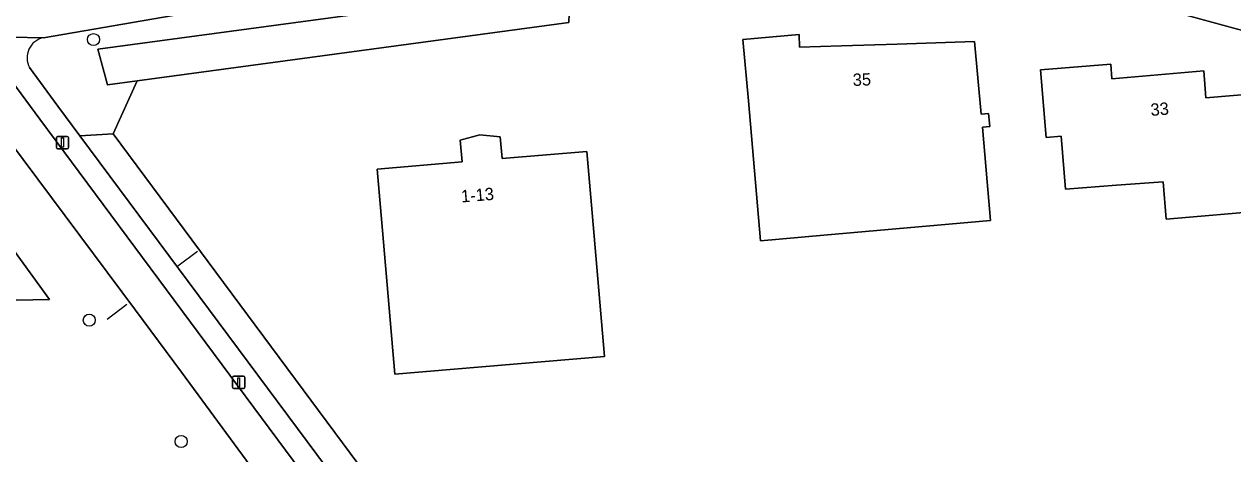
# Model space of a CAD drawing. Extents: x 163426 to 164192, y 380329 to 381641.
# Drawn here: x 163929.3 to 164027.2, y 381022.4 to 381057.2 of the extents above; entities that cross this region are included whole.
import ezdxf

# ---------------------------------------------------------------- set-up
doc = ezdxf.new("R2010")
doc.units = 0
for name, color, linetype in [('IMGEO_Boom', 7, 'Continuous'), ('IMGEO_Erf', 7, 'Continuous'), ('IMGEO_Fietspad_open', 7, 'Continuous'), ('IMGEO_Groenvoorziening', 7, 'Continuous'), ('IMGEO_Hek', 7, 'Continuous'), ('IMGEO_Lichtmast', 7, 'Continuous'), ('IMGEO_Pand', 7, 'Continuous'), ('IMGEO_Pand_nummerreeks', 7, 'Continuous'), ('IMGEO_Voetpad_open', 7, 'Continuous'), ('IMGEO_Waterloop', 7, 'Continuous')]:
    doc.layers.add(name, color=color, linetype=linetype)

msp = doc.modelspace()

# ---------------------------------------------------------------- linework, layer by layer
at = {"layer": 'IMGEO_Boom'}
for centre in [(163934.865, 381055.935), (163934.525, 381033.187), (163941.967, 381023.352)]:
    msp.add_circle(centre, 0.489, dxfattribs=at)
at = {"layer": 'IMGEO_Erf'}
for points in [[(163985.881, 381065.478), (163983.854, 381065.112), (163984.176, 381061.429), (163980.662, 381061.081), (163975.886, 381060.609), (163976.037, 381058.881), (163973.427, 381058.717), (163973.385, 381057.316), (163938.396, 381052.589), (163936.474, 381048.305), (163965.302, 381009.415), (163968.142, 381005.578), (163988.801, 381010.675), (164000, 381012.925), (164008.796, 381014.693), (164009.7, 381016.026), (164011.181, 381014.28), (164018.059, 381014.961)], [(164043.334, 381052.508), (164030.06, 381056.092), (164000, 381064.325), (163998.958, 381064.61)]]:
    msp.add_lwpolyline(points, dxfattribs=at)
for points in [[(164007.555, 381041.264), (163994.055, 381040.08), (163988.924, 381039.63), (163987.93, 381050.973), (163987.494, 381055.953), (163992.048, 381056.338), (163992.062, 381055.311), (163995.474, 381055.422), (164000, 381055.569), (164006.256, 381055.772), (164006.802, 381049.899), (164007.399, 381049.95), (164007.493, 381048.875), (164006.894, 381048.822), (164007.199, 381045.335)], [(164021.799, 381041.375), (164021.544, 381044.41), (164017.775, 381044.125), (164013.628, 381043.811), (164013.269, 381048.094), (164012.073, 381047.993), (164011.614, 381053.471), (164017.291, 381053.948), (164017.39, 381052.763), (164024.83, 381053.387), (164025.011, 381051.208), (164029.159, 381051.553), (164029.579, 381046.571), (164029.957, 381042.08)], [(163976.272, 381030.236), (163959.272, 381028.818), (163958.277, 381040.458), (163957.849, 381045.441), (163964.738, 381046.025), (163964.569, 381047.787), (163966.173, 381048.199), (163967.823, 381048.056), (163967.969, 381046.291), (163974.846, 381046.87), (163975.273, 381041.889)]]:
    msp.add_lwpolyline(points, close=True, dxfattribs=at)
at = {"layer": 'IMGEO_Fietspad_open'}
for points in [[(163966.446, 381001.057), (163930.523, 381049.491), (163926.717, 381054.622), (163925.556, 381056.187)], [(163923.219, 381054.202), (163924.27, 381052.792), (163924.402, 381052.616), (163926.35, 381050.002), (163928.061, 381047.708), (163938.279, 381034.003), (163942.009, 381028.965), (163953.161, 381013.78), (163961.45, 381002.494)]]:
    msp.add_lwpolyline(points, dxfattribs=at)
at = {"layer": 'IMGEO_Groenvoorziening'}
for points in [[(163975.886, 381060.609), (163980.662, 381061.081), (163980.593, 381061.81), (163977.128, 381061.219), (163976.661, 381063.908), (163971.248, 381063.001), (163957.475, 381060.692), (163930.805, 381056.087)], [(163929.685, 381053.658), (163931.981, 381050.546), (163933.77, 381048.138), (163936.474, 381048.305), (163938.396, 381052.589), (163936.002, 381052.266), (163935.728, 381053.26), (163935.208, 381055.15), (163971.524, 381060.07), (163973.475, 381060.334), (163973.427, 381058.717), (163976.037, 381058.881), (163975.886, 381060.609)], [(163942.009, 381028.965), (163938.279, 381034.003), (163928.061, 381047.708), (163926.35, 381050.002), (163923.656, 381045.375), (163931.3, 381034.851), (163923.206, 381034.692), (163914.286, 381019.455)], [(163961.45, 381002.494), (163953.161, 381013.78), (163942.009, 381028.965)]]:
    msp.add_lwpolyline(points, dxfattribs=at)
for points in [[(163936.474, 381048.305), (163933.77, 381048.138), (163965.814, 381005.004), (163968.142, 381005.578), (163965.302, 381009.415)], [(163904.614, 381014.127), (163918.118, 381011.99), (163914.286, 381019.455), (163923.206, 381034.692), (163931.3, 381034.851), (163923.656, 381045.375), (163922.795, 381043.895), (163906.633, 381016.132), (163905.062, 381016.099)]]:
    msp.add_lwpolyline(points, close=True, dxfattribs=at)
msp.add_arc((163931.144, 381054.458), 1.664, 101.76009, 208.73152, dxfattribs=at)
at = {"layer": 'IMGEO_Hek'}
for points in [[(163943.306, 381038.754), (163941.702, 381037.553)], [(163937.569, 381034.464), (163935.977, 381033.256)]]:
    msp.add_lwpolyline(points, dxfattribs=at)
at = {"layer": 'IMGEO_Lichtmast'}
for p, q in [((163931.857, 381047.187), (163931.857, 381047.987)), ((163931.857, 381047.987), (163931.857, 381047.187)), ((163931.957, 381048.087), (163932.747, 381048.087)), ((163932.747, 381048.087), (163931.957, 381048.087)), ((163932.847, 381047.987), (163932.847, 381047.187)), ((163932.847, 381047.187), (163932.847, 381047.987)), ((163932.747, 381047.087), (163931.957, 381047.087)), ((163931.957, 381047.087), (163932.747, 381047.087)), ((163946.141, 381027.746), (163946.141, 381028.546)), ((163946.141, 381028.546), (163946.141, 381027.746)), ((163946.241, 381028.646), (163947.031, 381028.646)), ((163947.031, 381028.646), (163946.241, 381028.646)), ((163947.131, 381028.546), (163947.131, 381027.746)), ((163947.131, 381027.746), (163947.131, 381028.546)), ((163947.031, 381027.646), (163946.241, 381027.646)), ((163946.241, 381027.646), (163947.031, 381027.646))]:
    msp.add_line(p, q, dxfattribs=at)
for points in [[(163932.277, 381047.962), (163932.427, 381047.962), (163932.427, 381047.212), (163932.277, 381047.212), (163932.277, 381047.962)], [(163946.561, 381028.521), (163946.711, 381028.521), (163946.711, 381027.771), (163946.561, 381027.771), (163946.561, 381028.521)]]:
    msp.add_lwpolyline(points, dxfattribs=at)
for centre, start, end in [((163931.957, 381047.987), 90, 180), ((163931.957, 381047.987), 90, 180), ((163932.747, 381047.987), 0, 90), ((163932.747, 381047.987), 360, 90), ((163931.957, 381047.187), 180, 270), ((163931.957, 381047.187), 180, 270), ((163932.747, 381047.187), 270, 0), ((163932.747, 381047.187), 270, 0), ((163946.241, 381028.546), 90, 180), ((163946.241, 381028.546), 90, 180), ((163947.031, 381028.546), 0, 90), ((163947.031, 381028.546), 360, 90), ((163946.241, 381027.746), 180, 270), ((163946.241, 381027.746), 180, 270), ((163947.031, 381027.746), 270, 0), ((163947.031, 381027.746), 270, 0)]:
    msp.add_arc(centre, 0.1, start, end, dxfattribs=at)
at = {"layer": 'IMGEO_Pand'}
for points in [[(164006.256, 381055.772), (164000, 381055.569), (163995.474, 381055.422), (163992.062, 381055.311), (163992.048, 381056.338), (163987.494, 381055.953), (163987.93, 381050.973), (163988.924, 381039.63), (163994.055, 381040.08), (164007.555, 381041.264), (164007.199, 381045.335), (164006.894, 381048.822), (164007.493, 381048.875), (164007.399, 381049.95), (164006.802, 381049.899)], [(164029.159, 381051.553), (164025.011, 381051.208), (164024.83, 381053.387), (164017.39, 381052.763), (164017.291, 381053.948), (164011.614, 381053.471), (164012.073, 381047.993), (164013.269, 381048.094), (164013.628, 381043.811), (164017.775, 381044.125), (164021.544, 381044.41), (164021.799, 381041.375), (164029.957, 381042.08), (164029.579, 381046.571)], [(163959.272, 381028.818), (163976.272, 381030.236), (163975.273, 381041.889), (163974.846, 381046.87), (163967.969, 381046.291), (163967.823, 381048.056), (163966.173, 381048.199), (163964.569, 381047.787), (163964.738, 381046.025), (163957.849, 381045.441), (163958.277, 381040.458)]]:
    msp.add_lwpolyline(points, close=True, dxfattribs=at)
at = {"layer": 'IMGEO_Voetpad_open'}
for points in [[(163998.958, 381064.61), (164000, 381064.325), (164030.06, 381056.092), (164030.721, 381058.549), (164029.304, 381058.985), (164024.363, 381060.339), (164000, 381066.992)], [(163925.556, 381056.187), (163930.805, 381056.087), (163957.475, 381060.692), (163971.248, 381063.001), (163976.661, 381063.908), (163980.336, 381064.524), (163983.854, 381065.112), (163985.881, 381065.478)], [(163930.805, 381056.087), (163925.556, 381056.187), (163926.717, 381054.622), (163930.523, 381049.491), (163966.446, 381001.057)], [(163933.77, 381048.138), (163931.981, 381050.546), (163929.685, 381053.658)], [(163969.654, 380999.835), (163969.531, 381000), (163965.814, 381005.004), (163933.77, 381048.138)]]:
    msp.add_lwpolyline(points, dxfattribs=at)
msp.add_arc((163931.144, 381054.458), 1.664, 101.76009, 208.73152, dxfattribs=at)
at = {"layer": 'IMGEO_Waterloop'}
msp.add_lwpolyline([(163973.385, 381057.316), (163973.427, 381058.717), (163973.475, 381060.334), (163971.524, 381060.07), (163935.208, 381055.15), (163935.728, 381053.26), (163936.002, 381052.266), (163938.396, 381052.589)], close=True, dxfattribs=at)

# ---------------------------------------------------------------- texts
at = {"layer": 'IMGEO_Pand_nummerreeks'}
for s, rotation, p in [('35', 1.86211, (163996.402, 381052.171)), ('33', 4.79566, (164020.56, 381049.738)), ('1-13', 4.80576, (163964.687, 381042.725))]:
    msp.add_text(s, height=1, rotation=rotation, dxfattribs=at).set_placement(p)

doc.saveas('drawing.dxf')
